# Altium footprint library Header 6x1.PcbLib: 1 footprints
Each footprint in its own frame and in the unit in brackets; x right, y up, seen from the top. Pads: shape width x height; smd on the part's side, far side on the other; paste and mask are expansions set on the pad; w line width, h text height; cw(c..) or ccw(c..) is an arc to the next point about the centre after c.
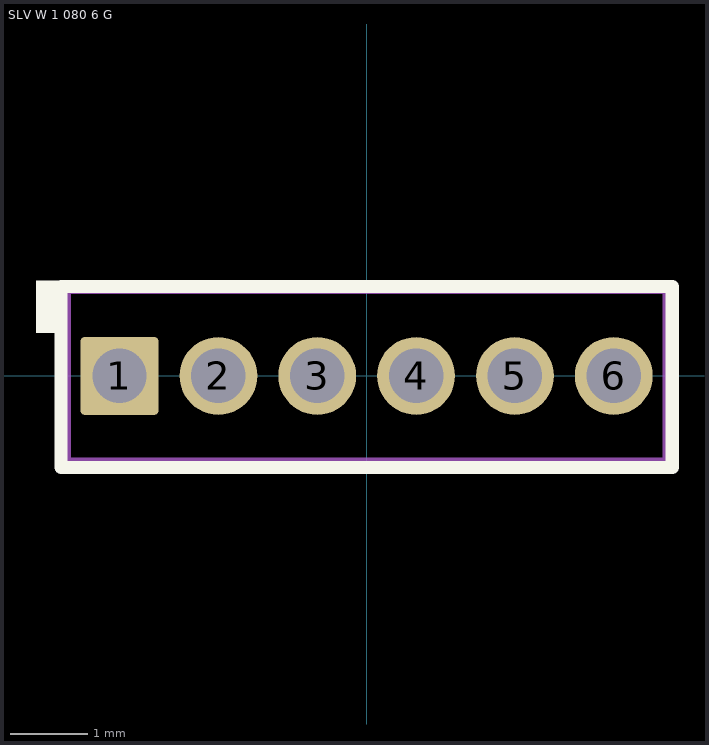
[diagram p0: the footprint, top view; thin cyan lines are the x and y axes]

## SLV W 1 080 6 G [mm] "SULLINS"
height 4
pads (6):
  rrect10% 1x1 hole 0.7: 1(-3.175,0)
  round 1 hole 0.7: 2(-1.905,0) 3(-0.635,0) 4(0.635,0) 5(1.905,0) 6(3.175,0)
Top Overlay:
  rectangle: -4.25,0.55 -3.925,1.225
  lines w0.17: -3.925,-1.175 3.925,-1.175 3.925,-0.25 3.925,0.825 3.925,1.15 -3.925,1.15 -3.925,0.125 -3.925,-1.175
M5 Assembly Top:
  lines w0.1: -3.85,-1.1 3.85,-1.1 3.85,1.1 -3.85,1.1 -3.85,-1.1
  text ".Designator" at -1.9,-0.5 h1.02
3D body: height 1, standoff 0, extent -3.849,-1.099 3.849,1.099
3D body: height 12.2, standoff -2.5, extent -0.835,-0.2 -0.435,0.2
3D body: height 12.2, standoff -2.5, extent -3.375,-0.2 -2.975,0.2
3D body: height 12.2, standoff -2.5, extent -2.105,-0.2 -1.705,0.2
3D body: height 12.2, standoff -2.5, extent 0.435,-0.2 0.835,0.2
3D body: height 12.2, standoff -2.5, extent 1.705,-0.2 2.105,0.2
3D body: height 12.2, standoff -2.5, extent 2.975,-0.2 3.375,0.2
